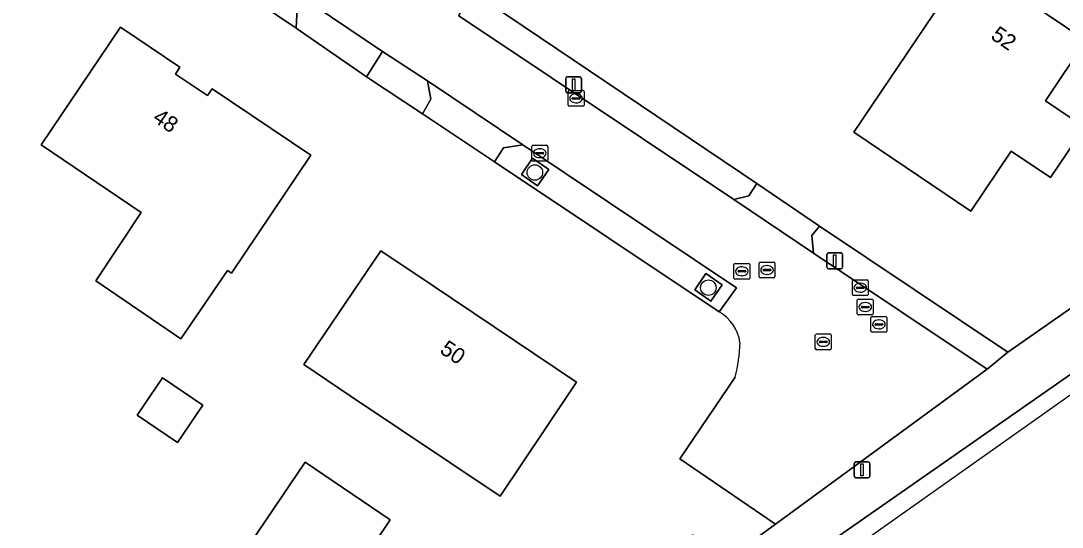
# Model space of a CAD drawing. Extents: x 163266 to 164362, y 381528 to 382286.
# Drawn here: x 164107.1 to 164172.9, y 381715.5 to 381747.5 of the extents above; entities that cross this region are included whole.
import ezdxf

# ---------------------------------------------------------------- set-up
doc = ezdxf.new("R2010")
doc.units = 0
for name, color, linetype in [('IMGEO_Boom', 7, 'Continuous'), ('IMGEO_Erf', 7, 'Continuous'), ('IMGEO_Groenvoorziening', 7, 'Continuous'), ('IMGEO_Haag', 7, 'Continuous'), ('IMGEO_Kolk', 7, 'Continuous'), ('IMGEO_Lichtmast', 7, 'Continuous'), ('IMGEO_Pand', 7, 'Continuous'), ('IMGEO_Pand_nummerreeks', 7, 'Continuous'), ('IMGEO_Rijbaan_lokaal_open', 7, 'Continuous'), ('IMGEO_Rioolput', 7, 'Continuous'), ('IMGEO_Voetpad_halfverhard', 7, 'Continuous'), ('IMGEO_Voetpad_open', 7, 'Continuous'), ('IMGEO_Waterloop', 7, 'Continuous')]:
    doc.layers.add(name, color=color, linetype=linetype)

msp = doc.modelspace()

# ---------------------------------------------------------------- linework, layer by layer
at = {"layer": 'IMGEO_Boom'}
for centre in [(164139.601, 381737.93), (164150.563, 381730.65)]:
    msp.add_circle(centre, 0.489, dxfattribs=at)
at = {"layer": 'IMGEO_Erf'}
for points in [[(164137.052, 381738.606), (164132.496, 381741.641), (164128.958, 381743.983), (164124.51, 381747.062), (164122.136, 381748.652), (164121.018, 381749.415), (164112.795, 381754.939), (164106.054, 381759.504), (164093.962, 381767.632), (164089.592, 381770.644), (164080.587, 381776.69), (164079.484, 381777.468), (164069.912, 381783.85), (164069.729, 381783.972)], [(164135.698, 381749.337), (164153.631, 381737.233), (164157.585, 381734.533), (164157.639, 381734.496), (164169.482, 381726.579), (164193.087, 381743.054), (164203.466, 381750.298), (164192.972, 381762.738), (164193.25, 381763.009), (164191.699, 381764.664), (164171.914, 381775.46), (164168.629, 381770.603), (164166.541, 381772.015), (164163.689, 381767.316), (164161.842, 381768.566), (164161.422, 381767.944), (164159.152, 381769.479), (164159.572, 381770.101), (164156.657, 381772.073), (164159.738, 381776.629), (164157.882, 381777.884), (164160.086, 381781.142), (164154.295, 381783.529)], [(164151.237, 381729.12), (164137.052, 381738.606)], [(164031.559, 381727.86), (164063.287, 381706.457), (164064.424, 381705.642), (164066.43, 381704.274), (164071.069, 381701.241), (164082.518, 381693.469), (164087.121, 381690.39), (164089.32, 381688.957), (164093.825, 381685.899), (164104.06, 381678.938), (164146.786, 381709.887), (164146.237, 381710.272), (164149.576, 381715.022), (164151.746, 381713.502), (164150.775, 381712.777), (164154.802, 381715.694), (164148.759, 381719.82), (164152.254, 381724.987)]]:
    msp.add_lwpolyline(points, dxfattribs=at)
for points in [[(164174.422, 381746.272), (164171.853, 381742.468), (164174.324, 381740.8), (164172.17, 381737.609), (164169.7, 381739.276), (164167.143, 381735.489), (164159.758, 381740.475), (164167.028, 381751.264)], [(164114.732, 381735.393), (164108.407, 381739.688), (164113.426, 381747.129), (164117.168, 381744.593), (164116.895, 381744.157), (164118.909, 381742.798), (164119.2, 381743.229), (164125.439, 381739.017), (164120.426, 381731.564), (164120.18, 381731.729), (164117.234, 381727.408), (164111.863, 381731.084)], [(164129.858, 381732.987), (164133.114, 381730.8), (164142.228, 381724.669), (164140.264, 381721.739), (164137.398, 381717.465), (164127.932, 381723.818), (164125.003, 381725.784)], [(164116.074, 381724.94), (164118.617, 381723.221), (164117.021, 381720.865), (164114.478, 381722.584)], [(164125.081, 381719.609), (164130.464, 381715.97), (164130.292, 381715.717), (164124.045, 381706.473), (164118.656, 381710.123)]]:
    msp.add_lwpolyline(points, close=True, dxfattribs=at)
for centre, radius, start, end in [((164149.918, 381726.8), 2.668, 8.11784, 60.38451), ((164142.097, 381727.523), 10.469, 345.98325, 358.10832)]:
    msp.add_arc(centre, radius, start, end, dxfattribs=at)
at = {"layer": 'IMGEO_Groenvoorziening'}
msp.add_lwpolyline([(164065.264, 381649.662), (164156.785, 381713.541), (164157.257, 381712.803), (164157.42, 381712.548), (164158.727, 381713.473), (164158.575, 381713.75), (164158.162, 381714.503), (164205.682, 381747.67), (164203.466, 381750.298), (164193.087, 381743.054), (164169.482, 381726.579), (164168.185, 381725.503), (164154.802, 381715.694), (164150.775, 381712.777), (164146.847, 381709.844), (164146.786, 381709.887), (164104.06, 381678.938)], dxfattribs=at)
for points in [[(164140.485, 381738.117), (164139.459, 381738.832), (164138.744, 381737.806), (164139.77, 381737.092)], [(164151.437, 381730.821), (164150.411, 381731.536), (164149.697, 381730.511), (164150.722, 381729.796)]]:
    msp.add_lwpolyline(points, close=True, dxfattribs=at)
at = {"layer": 'IMGEO_Haag'}
for points in [[(164140.485, 381738.117), (164139.459, 381738.832), (164138.744, 381737.806), (164139.77, 381737.092)], [(164151.437, 381730.821), (164150.411, 381731.536), (164149.697, 381730.511), (164150.722, 381729.796)]]:
    msp.add_lwpolyline(points, close=True, dxfattribs=at)
at = {"layer": 'IMGEO_Kolk'}
for p, q in [((164141.778, 381743.116), (164142.63, 381743.116)), ((164141.703, 381742.19), (164141.703, 381743.042)), ((164141.962, 381742.61), (164141.962, 381742.622)), ((164142.4, 381742.573), (164142.002, 381742.573)), ((164142.005, 381742.659), (164142.403, 381742.659)), ((164142.191, 381742.896), (164142.216, 381742.896)), ((164142.446, 381742.622), (164142.446, 381742.61)), ((164142.704, 381743.042), (164142.704, 381742.19)), ((164142.63, 381742.116), (164141.778, 381742.116)), ((164142.214, 381742.336), (164142.189, 381742.336)), ((164139.41, 381738.723), (164139.41, 381739.575)), ((164139.485, 381739.649), (164140.337, 381739.649)), ((164139.712, 381739.192), (164140.11, 381739.192)), ((164139.898, 381739.429), (164139.923, 381739.429)), ((164140.411, 381739.575), (164140.411, 381738.723)), ((164140.337, 381738.649), (164139.485, 381738.649)), ((164139.669, 381739.143), (164139.669, 381739.155)), ((164140.107, 381739.106), (164139.709, 381739.106)), ((164139.921, 381738.869), (164139.896, 381738.869)), ((164140.153, 381739.155), (164140.153, 381739.143)), ((164159.659, 381730.22), (164159.659, 381731.072)), ((164159.734, 381731.146), (164160.586, 381731.146)), ((164159.918, 381730.64), (164159.918, 381730.652)), ((164159.961, 381730.689), (164160.359, 381730.689)), ((164160.147, 381730.926), (164160.172, 381730.926)), ((164160.402, 381730.652), (164160.402, 381730.64)), ((164160.66, 381731.072), (164160.66, 381730.22)), ((164160.586, 381730.146), (164159.734, 381730.146)), ((164160.356, 381730.603), (164159.958, 381730.603)), ((164160.17, 381730.366), (164160.145, 381730.366)), ((164157.319, 381726.795), (164157.319, 381727.647)), ((164157.394, 381727.721), (164158.246, 381727.721)), ((164157.807, 381727.501), (164157.832, 381727.501)), ((164158.32, 381727.647), (164158.32, 381726.795)), ((164158.246, 381726.721), (164157.394, 381726.721)), ((164157.578, 381727.215), (164157.578, 381727.227)), ((164158.016, 381727.178), (164157.618, 381727.178)), ((164157.621, 381727.264), (164158.019, 381727.264)), ((164157.83, 381726.941), (164157.805, 381726.941)), ((164158.062, 381727.227), (164158.062, 381727.215))]:
    msp.add_line(p, q, dxfattribs=at)
for points in [[(164141.778, 381743.116), (164142.63, 381743.116)], [(164141.703, 381742.19), (164141.703, 381743.042)], [(164142.704, 381743.042), (164142.704, 381742.19)], [(164142.63, 381742.116), (164141.778, 381742.116)], [(164139.41, 381738.723), (164139.41, 381739.575)], [(164139.485, 381739.649), (164140.337, 381739.649)], [(164140.411, 381739.575), (164140.411, 381738.723)], [(164140.337, 381738.649), (164139.485, 381738.649)], [(164159.659, 381730.22), (164159.659, 381731.072)], [(164159.734, 381731.146), (164160.586, 381731.146)], [(164160.66, 381731.072), (164160.66, 381730.22)], [(164160.586, 381730.146), (164159.734, 381730.146)], [(164157.319, 381726.795), (164157.319, 381727.647)], [(164157.394, 381727.721), (164158.246, 381727.721)], [(164158.32, 381727.647), (164158.32, 381726.795)], [(164158.246, 381726.721), (164157.394, 381726.721)]]:
    msp.add_lwpolyline(points, dxfattribs=at)
for centre, radius, start, end in [((164141.78, 381743.04), 0.0765, 91.55205, 178.44795), ((164141.78, 381743.04), 0.0765, 91.55205, 178.44795), ((164142.628, 381743.04), 0.0765, 1.55205, 88.44795), ((164142.628, 381743.04), 0.0765, 1.55205, 88.44795), ((164142.002, 381742.619), 0.0403, 85.87752, 175.75265), ((164141.999, 381742.609), 0.0366, 178.93798, 274.71019), ((164142.403, 381742.616), 0.043, 264.86636, 352.45326), ((164142.407, 381742.621), 0.0386, 1.73085, 96.63898), ((164141.78, 381742.192), 0.0765, 181.55205, 268.44795), ((164141.78, 381742.192), 0.0765, 181.55205, 268.44795), ((164142.628, 381742.192), 0.0765, 271.55205, 358.44795), ((164142.628, 381742.192), 0.0765, 271.55205, 358.44795), ((164139.487, 381739.573), 0.0765, 91.55205, 178.44795), ((164139.487, 381739.573), 0.0765, 91.55205, 178.44795), ((164139.709, 381739.152), 0.0403, 85.87752, 175.75265), ((164140.114, 381739.154), 0.0386, 1.73085, 96.63898), ((164140.335, 381739.573), 0.0765, 1.55205, 88.44795), ((164140.335, 381739.573), 0.0765, 1.55205, 88.44795), ((164139.487, 381738.725), 0.0765, 181.55205, 268.44795), ((164139.487, 381738.725), 0.0765, 181.55205, 268.44795), ((164139.706, 381739.142), 0.0366, 178.93798, 274.71019), ((164140.11, 381739.149), 0.043, 264.86636, 352.45326), ((164140.335, 381738.725), 0.0765, 271.55205, 358.44795), ((164140.335, 381738.725), 0.0765, 271.55205, 358.44795), ((164159.736, 381731.07), 0.0765, 91.55205, 178.44795), ((164159.736, 381731.07), 0.0765, 91.55205, 178.44795), ((164159.958, 381730.649), 0.0403, 85.87752, 175.75265), ((164159.955, 381730.639), 0.0366, 178.93798, 274.71019), ((164160.359, 381730.646), 0.043, 264.86636, 352.45326), ((164160.363, 381730.651), 0.0386, 1.73085, 96.63898), ((164160.584, 381731.07), 0.0765, 1.55205, 88.44795), ((164160.584, 381731.07), 0.0765, 1.55205, 88.44795), ((164159.736, 381730.222), 0.0765, 181.55205, 268.44795), ((164159.736, 381730.222), 0.0765, 181.55205, 268.44795), ((164160.584, 381730.222), 0.0765, 271.55205, 358.44795), ((164160.584, 381730.222), 0.0765, 271.55205, 358.44795), ((164157.396, 381727.645), 0.0765, 91.55205, 178.44795), ((164157.396, 381727.645), 0.0765, 91.55205, 178.44795), ((164158.244, 381727.645), 0.0765, 1.55205, 88.44795), ((164158.244, 381727.645), 0.0765, 1.55205, 88.44795), ((164157.396, 381726.797), 0.0765, 181.55205, 268.44795), ((164157.396, 381726.797), 0.0765, 181.55205, 268.44795), ((164157.618, 381727.224), 0.0403, 85.87752, 175.75265), ((164157.615, 381727.214), 0.0366, 178.93798, 274.71019), ((164158.019, 381727.221), 0.043, 264.86636, 352.45326), ((164158.023, 381727.226), 0.0386, 1.73085, 96.63898), ((164158.244, 381726.797), 0.0765, 271.55205, 358.44795), ((164158.244, 381726.797), 0.0765, 271.55205, 358.44795)]:
    msp.add_arc(centre, radius, start, end, dxfattribs=at)
for centre, major_axis, ratio, start_param, end_param in [((164142.19, 381742.616), (-0.387, 0.002), 0.722429, 4.712389, 7.853982), ((164142.215, 381742.616), (-0.39, 0.002), 0.717154, 1.570796, 4.712389), ((164139.897, 381739.149), (-0.387, 0.002), 0.722429, 4.712389, 7.853982), ((164139.922, 381739.149), (-0.39, 0.002), 0.717154, 1.570796, 4.712389), ((164160.146, 381730.646), (-0.387, 0.002), 0.722429, 4.712389, 7.853982), ((164160.171, 381730.646), (-0.39, 0.002), 0.717154, 1.570796, 4.712389), ((164157.806, 381727.221), (-0.387, 0.002), 0.722429, 4.712389, 7.853982), ((164157.831, 381727.221), (-0.39, 0.002), 0.717154, 1.570796, 4.712389)]:
    msp.add_ellipse(centre, major_axis=major_axis, ratio=ratio, start_param=start_param, end_param=end_param, dxfattribs=at)
at = {"layer": 'IMGEO_Lichtmast'}
for p, q in [((164141.549, 381743.072), (164141.549, 381743.872)), ((164141.549, 381743.872), (164141.549, 381743.072)), ((164141.649, 381743.972), (164142.439, 381743.972)), ((164142.439, 381743.972), (164141.649, 381743.972)), ((164142.539, 381743.872), (164142.539, 381743.072)), ((164142.539, 381743.072), (164142.539, 381743.872)), ((164142.439, 381742.972), (164141.649, 381742.972)), ((164141.649, 381742.972), (164142.439, 381742.972)), ((164158.055, 381731.942), (164158.055, 381732.742)), ((164158.055, 381732.742), (164158.055, 381731.942)), ((164158.155, 381732.842), (164158.945, 381732.842)), ((164158.945, 381732.842), (164158.155, 381732.842)), ((164159.045, 381732.742), (164159.045, 381731.942)), ((164159.045, 381731.942), (164159.045, 381732.742)), ((164158.945, 381731.842), (164158.155, 381731.842)), ((164158.155, 381731.842), (164158.945, 381731.842)), ((164159.778, 381718.733), (164159.778, 381719.533)), ((164159.778, 381719.533), (164159.778, 381718.733)), ((164159.878, 381719.633), (164160.668, 381719.633)), ((164160.668, 381719.633), (164159.878, 381719.633)), ((164160.768, 381719.533), (164160.768, 381718.733)), ((164160.768, 381718.733), (164160.768, 381719.533)), ((164160.668, 381718.633), (164159.878, 381718.633)), ((164159.878, 381718.633), (164160.668, 381718.633))]:
    msp.add_line(p, q, dxfattribs=at)
for points in [[(164141.969, 381743.847), (164142.119, 381743.847), (164142.119, 381743.097), (164141.969, 381743.097), (164141.969, 381743.847)], [(164158.475, 381732.717), (164158.625, 381732.717), (164158.625, 381731.967), (164158.475, 381731.967), (164158.475, 381732.717)], [(164160.198, 381719.508), (164160.348, 381719.508), (164160.348, 381718.758), (164160.198, 381718.758), (164160.198, 381719.508)]]:
    msp.add_lwpolyline(points, dxfattribs=at)
for centre, start, end in [((164141.649, 381743.872), 90, 180), ((164141.649, 381743.872), 90, 180), ((164142.439, 381743.872), 0, 90), ((164142.439, 381743.872), 360, 90), ((164141.649, 381743.072), 180, 270), ((164141.649, 381743.072), 180, 270), ((164142.439, 381743.072), 270, 0), ((164142.439, 381743.072), 270, 0), ((164158.155, 381732.742), 90, 180), ((164158.155, 381732.742), 90, 180), ((164158.945, 381732.742), 0, 90), ((164158.945, 381732.742), 360, 90), ((164158.155, 381731.942), 180, 270), ((164158.155, 381731.942), 180, 270), ((164158.945, 381731.942), 270, 0), ((164158.945, 381731.942), 270, 0), ((164159.878, 381719.533), 90, 180), ((164159.878, 381719.533), 90, 180), ((164160.668, 381719.533), 0, 90), ((164160.668, 381719.533), 360, 90), ((164159.878, 381718.733), 180, 270), ((164159.878, 381718.733), 180, 270), ((164160.668, 381718.733), 270, 0), ((164160.668, 381718.733), 270, 0)]:
    msp.add_arc(centre, 0.1, start, end, dxfattribs=at)
at = {"layer": 'IMGEO_Pand'}
for points in [[(164167.143, 381735.489), (164169.7, 381739.276), (164172.17, 381737.609), (164174.324, 381740.8), (164171.853, 381742.468), (164174.422, 381746.272), (164167.028, 381751.264), (164159.758, 381740.475)], [(164117.168, 381744.593), (164113.426, 381747.129), (164108.407, 381739.688), (164114.732, 381735.393), (164111.863, 381731.084), (164117.234, 381727.408), (164120.18, 381731.729), (164120.426, 381731.564), (164125.439, 381739.017), (164119.2, 381743.229), (164118.909, 381742.798), (164116.895, 381744.157)], [(164129.858, 381732.987), (164125.003, 381725.784), (164127.932, 381723.818), (164137.398, 381717.465), (164140.264, 381721.739), (164142.228, 381724.669), (164133.114, 381730.8)], [(164114.478, 381722.584), (164117.021, 381720.865), (164118.617, 381723.221), (164116.074, 381724.94)], [(164125.081, 381719.609), (164118.656, 381710.123), (164124.045, 381706.473), (164130.292, 381715.717), (164130.464, 381715.97)]]:
    msp.add_lwpolyline(points, close=True, dxfattribs=at)
at = {"layer": 'IMGEO_Rijbaan_lokaal_open'}
for points in [[(164070.053, 381785.812), (164070.885, 381785.296), (164075.854, 381781.95), (164080.444, 381778.871), (164081.576, 381778.113), (164090.01, 381772.472), (164095.526, 381768.712), (164106.992, 381760.997), (164114.512, 381755.966), (164122.083, 381750.893), (164123.208, 381750.173), (164124.631, 381749.205), (164129.98, 381745.578), (164132.813, 381743.736), (164138.834, 381739.683), (164152.333, 381730.648), (164151.237, 381729.12)], [(164152.254, 381724.987), (164148.759, 381719.82), (164154.802, 381715.694), (164168.185, 381725.503), (164157.214, 381732.837), (164152.161, 381736.215), (164134.849, 381747.788), (164134.766, 381747.851)]]:
    msp.add_lwpolyline(points, dxfattribs=at)
for centre, radius, start, end in [((164149.918, 381726.8), 2.668, 8.11784, 60.38451), ((164142.097, 381727.523), 10.469, 345.98325, 358.10832)]:
    msp.add_arc(centre, radius, start, end, dxfattribs=at)
at = {"layer": 'IMGEO_Rioolput'}
for p, q in [((164152.176, 381731.261), (164152.176, 381732.113)), ((164152.251, 381732.187), (164153.103, 381732.187)), ((164152.664, 381731.967), (164152.689, 381731.967)), ((164153.177, 381732.113), (164153.177, 381731.261)), ((164153.768, 381731.341), (164153.768, 381732.193)), ((164153.843, 381732.267), (164154.695, 381732.267)), ((164154.256, 381732.047), (164154.281, 381732.047)), ((164154.769, 381732.193), (164154.769, 381731.341)), ((164152.435, 381731.681), (164152.435, 381731.693)), ((164152.873, 381731.644), (164152.475, 381731.644)), ((164152.478, 381731.73), (164152.876, 381731.73)), ((164152.687, 381731.407), (164152.662, 381731.407)), ((164152.919, 381731.693), (164152.919, 381731.681)), ((164154.027, 381731.761), (164154.027, 381731.773)), ((164154.465, 381731.724), (164154.067, 381731.724)), ((164154.07, 381731.81), (164154.468, 381731.81)), ((164154.279, 381731.487), (164154.254, 381731.487)), ((164154.511, 381731.773), (164154.511, 381731.761)), ((164153.103, 381731.187), (164152.251, 381731.187)), ((164154.695, 381731.267), (164153.843, 381731.267)), ((164159.973, 381729), (164159.973, 381729.852)), ((164160.048, 381729.926), (164160.9, 381729.926)), ((164160.232, 381729.42), (164160.232, 381729.432)), ((164160.67, 381729.383), (164160.272, 381729.383)), ((164160.275, 381729.469), (164160.673, 381729.469)), ((164160.461, 381729.706), (164160.486, 381729.706)), ((164160.716, 381729.432), (164160.716, 381729.42)), ((164160.974, 381729.852), (164160.974, 381729)), ((164160.9, 381728.926), (164160.048, 381728.926)), ((164160.484, 381729.146), (164160.459, 381729.146)), ((164160.836, 381727.902), (164160.836, 381728.754)), ((164160.911, 381728.828), (164161.763, 381728.828)), ((164161.837, 381728.754), (164161.837, 381727.902)), ((164161.095, 381728.322), (164161.095, 381728.334)), ((164161.533, 381728.285), (164161.135, 381728.285)), ((164161.138, 381728.371), (164161.536, 381728.371)), ((164161.347, 381728.048), (164161.322, 381728.048)), ((164161.324, 381728.608), (164161.349, 381728.608)), ((164161.579, 381728.334), (164161.579, 381728.322)), ((164161.763, 381727.828), (164160.911, 381727.828))]:
    msp.add_line(p, q, dxfattribs=at)
for points in [[(164152.176, 381731.261), (164152.176, 381732.113)], [(164152.251, 381732.187), (164153.103, 381732.187)], [(164153.177, 381732.113), (164153.177, 381731.261)], [(164153.768, 381731.341), (164153.768, 381732.193)], [(164153.843, 381732.267), (164154.695, 381732.267)], [(164154.769, 381732.193), (164154.769, 381731.341)], [(164153.103, 381731.187), (164152.251, 381731.187)], [(164154.695, 381731.267), (164153.843, 381731.267)], [(164159.973, 381729), (164159.973, 381729.852)], [(164160.048, 381729.926), (164160.9, 381729.926)], [(164160.974, 381729.852), (164160.974, 381729)], [(164160.9, 381728.926), (164160.048, 381728.926)], [(164160.836, 381727.902), (164160.836, 381728.754)], [(164160.911, 381728.828), (164161.763, 381728.828)], [(164161.837, 381728.754), (164161.837, 381727.902)], [(164161.763, 381727.828), (164160.911, 381727.828)]]:
    msp.add_lwpolyline(points, dxfattribs=at)
for centre, radius, start, end in [((164152.253, 381732.111), 0.0765, 91.55205, 178.44795), ((164152.253, 381732.111), 0.0765, 91.55205, 178.44795), ((164153.101, 381732.111), 0.0765, 1.55205, 88.44795), ((164153.101, 381732.111), 0.0765, 1.55205, 88.44795), ((164153.845, 381732.191), 0.0765, 91.55205, 178.44795), ((164153.845, 381732.191), 0.0765, 91.55205, 178.44795), ((164154.693, 381732.191), 0.0765, 1.55205, 88.44795), ((164154.693, 381732.191), 0.0765, 1.55205, 88.44795), ((164152.475, 381731.69), 0.0403, 85.87752, 175.75265), ((164152.472, 381731.68), 0.0366, 178.93798, 274.71019), ((164152.876, 381731.687), 0.043, 264.86636, 352.45326), ((164152.88, 381731.692), 0.0386, 1.73085, 96.63898), ((164153.845, 381731.343), 0.0765, 181.55205, 268.44795), ((164153.845, 381731.343), 0.0765, 181.55205, 268.44795), ((164154.067, 381731.77), 0.0403, 85.87752, 175.75265), ((164154.064, 381731.76), 0.0366, 178.93798, 274.71019), ((164154.468, 381731.767), 0.043, 264.86636, 352.45326), ((164154.472, 381731.772), 0.0386, 1.73085, 96.63898), ((164154.693, 381731.343), 0.0765, 271.55205, 358.44795), ((164154.693, 381731.343), 0.0765, 271.55205, 358.44795), ((164152.253, 381731.263), 0.0765, 181.55205, 268.44795), ((164152.253, 381731.263), 0.0765, 181.55205, 268.44795), ((164153.101, 381731.263), 0.0765, 271.55205, 358.44795), ((164153.101, 381731.263), 0.0765, 271.55205, 358.44795), ((164160.05, 381729.85), 0.0765, 91.55205, 178.44795), ((164160.05, 381729.85), 0.0765, 91.55205, 178.44795), ((164160.272, 381729.429), 0.0403, 85.87752, 175.75265), ((164160.269, 381729.419), 0.0366, 178.93798, 274.71019), ((164160.673, 381729.426), 0.043, 264.86636, 352.45326), ((164160.677, 381729.431), 0.0386, 1.73085, 96.63898), ((164160.898, 381729.85), 0.0765, 1.55205, 88.44795), ((164160.898, 381729.85), 0.0765, 1.55205, 88.44795), ((164160.05, 381729.002), 0.0765, 181.55205, 268.44795), ((164160.05, 381729.002), 0.0765, 181.55205, 268.44795), ((164160.913, 381728.752), 0.0765, 91.55205, 178.44795), ((164160.913, 381728.752), 0.0765, 91.55205, 178.44795), ((164160.898, 381729.002), 0.0765, 271.55205, 358.44795), ((164160.898, 381729.002), 0.0765, 271.55205, 358.44795), ((164161.761, 381728.752), 0.0765, 1.55205, 88.44795), ((164161.761, 381728.752), 0.0765, 1.55205, 88.44795), ((164161.135, 381728.331), 0.0403, 85.87752, 175.75265), ((164161.132, 381728.321), 0.0366, 178.93798, 274.71019), ((164161.536, 381728.328), 0.043, 264.86636, 352.45326), ((164161.54, 381728.333), 0.0386, 1.73085, 96.63898), ((164160.913, 381727.904), 0.0765, 181.55205, 268.44795), ((164160.913, 381727.904), 0.0765, 181.55205, 268.44795), ((164161.761, 381727.904), 0.0765, 271.55205, 358.44795), ((164161.761, 381727.904), 0.0765, 271.55205, 358.44795)]:
    msp.add_arc(centre, radius, start, end, dxfattribs=at)
for centre, major_axis, ratio, start_param, end_param in [((164152.663, 381731.687), (-0.387, 0.002), 0.722429, 4.712389, 7.853982), ((164152.688, 381731.687), (-0.39, 0.002), 0.717154, 1.570796, 4.712389), ((164154.255, 381731.767), (-0.387, 0.002), 0.722429, 4.712389, 7.853982), ((164154.28, 381731.767), (-0.39, 0.002), 0.717154, 1.570796, 4.712389), ((164160.46, 381729.426), (-0.387, 0.002), 0.722429, 4.712389, 7.853982), ((164160.485, 381729.426), (-0.39, 0.002), 0.717154, 1.570796, 4.712389), ((164161.323, 381728.328), (-0.387, 0.002), 0.722429, 4.712389, 7.853982), ((164161.348, 381728.328), (-0.39, 0.002), 0.717154, 1.570796, 4.712389)]:
    msp.add_ellipse(centre, major_axis=major_axis, ratio=ratio, start_param=start_param, end_param=end_param, dxfattribs=at)
at = {"layer": 'IMGEO_Voetpad_halfverhard'}
for points in [[(164124.51, 381747.062), (164124.631, 381749.205), (164123.208, 381750.173), (164122.136, 381748.652)], [(164135.698, 381749.337), (164134.766, 381747.851), (164134.849, 381747.788), (164152.161, 381736.215), (164153.112, 381736.465), (164153.631, 381737.233)], [(164129.98, 381745.578), (164128.958, 381743.983), (164132.496, 381741.641), (164133.023, 381742.576), (164132.813, 381743.736)], [(164137.621, 381739.486), (164137.052, 381738.606), (164151.237, 381729.12), (164152.333, 381730.648), (164138.834, 381739.683)], [(164139.77, 381737.092), (164138.744, 381737.806), (164139.459, 381738.832), (164140.485, 381738.117)], [(164157.639, 381734.496), (164157.585, 381734.533), (164157.092, 381733.949), (164157.214, 381732.837), (164168.185, 381725.503), (164169.482, 381726.579)], [(164150.722, 381729.796), (164149.697, 381730.511), (164150.411, 381731.536), (164151.437, 381730.821)]]:
    msp.add_lwpolyline(points, close=True, dxfattribs=at)
at = {"layer": 'IMGEO_Voetpad_open'}
for points in [[(164124.51, 381747.062), (164128.958, 381743.983), (164129.98, 381745.578), (164124.631, 381749.205)], [(164137.052, 381738.606), (164137.621, 381739.486), (164138.834, 381739.683), (164132.813, 381743.736), (164133.023, 381742.576), (164132.496, 381741.641)], [(164153.631, 381737.233), (164153.112, 381736.465), (164152.161, 381736.215), (164157.214, 381732.837), (164157.092, 381733.949), (164157.585, 381734.533)]]:
    msp.add_lwpolyline(points, close=True, dxfattribs=at)
at = {"layer": 'IMGEO_Waterloop'}
msp.add_lwpolyline([(164206.853, 381748.497), (164205.682, 381747.67), (164158.162, 381714.503), (164158.575, 381713.75), (164158.727, 381713.473), (164207.386, 381747.928)], close=True, dxfattribs=at)

# ---------------------------------------------------------------- texts
at = {"layer": 'IMGEO_Pand_nummerreeks'}
for s, rotation, p in [('52', 325.66217, (164168.339, 381746.428)), ('48', 326.00291, (164115.388, 381741.217)), ('50', 326.08297, (164133.532, 381726.564))]:
    msp.add_text(s, height=1, rotation=rotation, dxfattribs=at).set_placement(p)

doc.saveas('drawing.dxf')
